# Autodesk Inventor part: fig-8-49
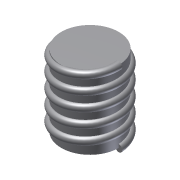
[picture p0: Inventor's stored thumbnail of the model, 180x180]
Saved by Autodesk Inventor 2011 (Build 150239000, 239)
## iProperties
Shininess: 77.0
Length Units: 11269
Angle Units: 11279
Time Units: 11290
Mass Units: 11283
Length Display Precision: 3
Angle Display Precision: 2
Created: 2002-01
Part Number: fig-8-49
Document SubType Name: Modeling
Designer: CADSoft
Density: 1 g/cm^3
Density: 0.0
Volumn: 0.0
Area: 0.0
PropertySet Name: Model Information
Control State: 0
Master: False
Checked Out: False
Author: CADSoft
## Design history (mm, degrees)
sketch "Sketch4"
  geometry: C1 r 20 at (0, 0)
  constraints: 1 centre point
  dimensions: "d44" = 40 diameter of C1
sketch "Sketch2"
  geometry: C1 r 2.5 at (-20, -0.092); 1 further point
  constraints: 1 centre point, 1 other
  dimensions: "d0" = 5 diameter of C1; "d43" = 20 horizontal distance of C1.centre point (0, 0)
extrude "Extrusion2" join sketch "Sketch4" distance "d45" = 50; taper "d46" = 0 deg
coil "Coil6" pitch "d47" = 10; turns "d49" = 5; dims "d48" = 10, "d50" = 0, angle "d51" = 90 deg, angle "d52" = 90 deg, "d53" = 0, "d54" = 0
body "Solid1"
